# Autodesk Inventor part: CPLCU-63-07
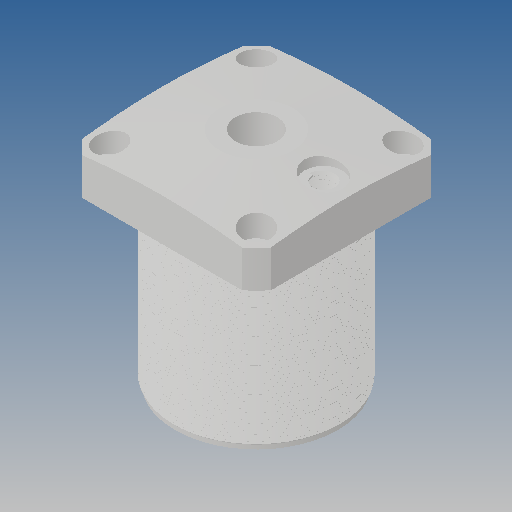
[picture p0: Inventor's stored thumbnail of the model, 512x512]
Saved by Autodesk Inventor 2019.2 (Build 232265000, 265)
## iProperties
Created: 2010-03
Part Number: CPLCU-63-07
Material: Ogólny
Document SubType Name: Modeling
Designer: CADENGINEERING4
Density: 1 g/cm^3
Appearance: Domyślna
Author: CADENGINEERING4
Revision Number: 4LAST_VERSION
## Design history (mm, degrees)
feature "Baza1"
node "Bryła1"
